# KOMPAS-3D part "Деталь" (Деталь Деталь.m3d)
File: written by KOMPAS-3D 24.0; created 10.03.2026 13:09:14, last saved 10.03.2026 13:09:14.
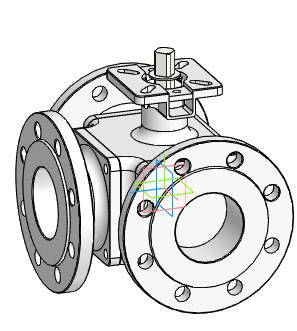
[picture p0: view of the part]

Document properties: Автор: R2D2; Полное имя файла: E:\Работа\Зайцев\BV3232P(4pc)-FP-3WL-F-ISO-H Кран шаровой DN.ru Ду15-100 Ру16\DN80\исходные материалы\Деталь Деталь.m3d

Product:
- Body: Твердое тело1  | qty 1
- Part/product: Деталь
    additional columns: Типовые

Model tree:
1. Твердое тело1  (labels: Твердое тело1)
